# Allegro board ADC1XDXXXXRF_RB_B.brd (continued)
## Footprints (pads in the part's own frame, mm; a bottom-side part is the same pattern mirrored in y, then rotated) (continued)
C6P6MMX6P6MM
  rect 3.81x1.27 smd: 1(-2.625,0) 2(2.625,0)
C10P3MMX10P3MM
  rect 4.15x1.9 smd: 1(-3.875,0) 2(3.875,0)
C0402
  rect 0.889x0.711 smd: 1(-0.648,0) 2(0.648,0)
C0402_NO_SS
  rect 0.406x0.508 smd: 1(-0.508,0) 2(0.508,0)
C0603
  rect 0.813x0.965 smd: 1(-0.711,0) 2(0.711,0)
C0805
  rect 1.27x1.27 smd: 1(-1.067,0) 2(1.067,0)
C1206
  rect 1.524x1.524 smd: 1(-1.651,0) 2(1.651,0)
C1210
  rect 1.626x2.54 smd: 1(-1.714,0) 2(1.714,0)
C3216
  rect 1.6x1.803 smd: 1(-1.6,0) 2(1.6,0)
CAP_C-CASE
  rect 2.692x3.404 smd: 1(-2.743,0) 2(2.743,0)
CHOKE_CM2545-B
  rect 2.032x2.032 hole 1.524: 1(-3.81,1.27)
  round 2.032 hole 1.524: 2(-3.81,-1.27) 3(3.81,-1.27) 4(3.81,1.27)
CONN_SEAM_040
  round 1.27 hole 1.295 unplated: (-27.191,0) (27.191,3.048)
  round 0.635 smd: A1(-24.765,-5.715) A2(-23.495,-5.715) A3(-22.225,-5.715) A4(-20.955,-5.715) A5(-19.685,-5.715) A6(-18.415,-5.715) A7(-17.145,-5.715) A8(-15.875,-5.715) A9(-14.605,-5.715) A10(-13.335,-5.715) A11(-12.065,-5.715) A12(-10.795,-5.715) A13(-9.525,-5.715) A14(-8.255,-5.715) A15(-6.985,-5.715) A16(-5.715,-5.715) A17(-4.445,-5.715) A18(-3.175,-5.715) A19(-1.905,-5.715) A20(-0.635,-5.715) A21(0.635,-5.715) A22(1.905,-5.715) A23(3.175,-5.715) A24(4.445,-5.715) A25(5.715,-5.715) A26(6.985,-5.715) A27(8.255,-5.715) A28(9.525,-5.715) A29(10.795,-5.715) A30(12.065,-5.715) A31(13.335,-5.715) A32(14.605,-5.715) A33(15.875,-5.715) A34(17.145,-5.715) A35(18.415,-5.715) A36(19.685,-5.715) A37(20.955,-5.715) A38(22.225,-5.715) A39(23.495,-5.715) A40(24.765,-5.715) B1(-24.765,-4.445) B2(-23.495,-4.445) B3(-22.225,-4.445) B4(-20.955,-4.445) B5(-19.685,-4.445) B6(-18.415,-4.445) B7(-17.145,-4.445) B8(-15.875,-4.445) B9(-14.605,-4.445) B10(-13.335,-4.445) B11(-12.065,-4.445) B12(-10.795,-4.445) B13(-9.525,-4.445) B14(-8.255,-4.445) B15(-6.985,-4.445) B16(-5.715,-4.445) B17(-4.445,-4.445) B18(-3.175,-4.445) B19(-1.905,-4.445) B20(-0.635,-4.445) B21(0.635,-4.445) B22(1.905,-4.445) B23(3.175,-4.445) B24(4.445,-4.445) B25(5.715,-4.445) B26(6.985,-4.445) B27(8.255,-4.445) B28(9.525,-4.445) B29(10.795,-4.445) B30(12.065,-4.445) B31(13.335,-4.445) B32(14.605,-4.445) B33(15.875,-4.445) B34(17.145,-4.445) B35(18.415,-4.445) B36(19.685,-4.445) B37(20.955,-4.445) B38(22.225,-4.445) B39(23.495,-4.445) B40(24.765,-4.445) C1(-24.765,-3.175) C2(-23.495,-3.175) C3(-22.225,-3.175) C4(-20.955,-3.175) C5(-19.685,-3.175) C6(-18.415,-3.175) C7(-17.145,-3.175) C8(-15.875,-3.175) C9(-14.605,-3.175) C10(-13.335,-3.175) C11(-12.065,-3.175) C12(-10.795,-3.175) C13(-9.525,-3.175) C14(-8.255,-3.175) C15(-6.985,-3.175) C16(-5.715,-3.175) C17(-4.445,-3.175) C18(-3.175,-3.175) C19(-1.905,-3.175) C20(-0.635,-3.175) C21(0.635,-3.175) C22(1.905,-3.175) C23(3.175,-3.175) C24(4.445,-3.175) C25(5.715,-3.175) C26(6.985,-3.175) C27(8.255,-3.175) C28(9.525,-3.175) C29(10.795,-3.175) C30(12.065,-3.175) C31(13.335,-3.175) C32(14.605,-3.175) C33(15.875,-3.175) C34(17.145,-3.175) C35(18.415,-3.175) C36(19.685,-3.175) C37(20.955,-3.175) C38(22.225,-3.175) C39(23.495,-3.175) C40(24.765,-3.175) D1(-24.765,-1.905) D2(-23.495,-1.905) D3(-22.225,-1.905) D4(-20.955,-1.905) D5(-19.685,-1.905) D6(-18.415,-1.905) D7(-17.145,-1.905) D8(-15.875,-1.905) D9(-14.605,-1.905) D10(-13.335,-1.905) D11(-12.065,-1.905) D12(-10.795,-1.905) D13(-9.525,-1.905) D14(-8.255,-1.905) D15(-6.985,-1.905) D16(-5.715,-1.905) D17(-4.445,-1.905) D18(-3.175,-1.905) D19(-1.905,-1.905) D20(-0.635,-1.905) D21(0.635,-1.905) D22(1.905,-1.905) D23(3.175,-1.905) D24(4.445,-1.905) D25(5.715,-1.905) D26(6.985,-1.905) D27(8.255,-1.905) D28(9.525,-1.905) D29(10.795,-1.905) D30(12.065,-1.905) D31(13.335,-1.905) D32(14.605,-1.905) D33(15.875,-1.905) D34(17.145,-1.905) D35(18.415,-1.905) D36(19.685,-1.905) D37(20.955,-1.905) D38(22.225,-1.905) D39(23.495,-1.905) D40(24.765,-1.905) E1(-24.765,-0.635) E2(-23.495,-0.635) E3(-22.225,-0.635) E4(-20.955,-0.635) E5(-19.685,-0.635) E6(-18.415,-0.635) E7(-17.145,-0.635) E8(-15.875,-0.635) E9(-14.605,-0.635) E10(-13.335,-0.635) E11(-12.065,-0.635) E12(-10.795,-0.635) E13(-9.525,-0.635) E14(-8.255,-0.635) E15(-6.985,-0.635) E16(-5.715,-0.635) E17(-4.445,-0.635) E18(-3.175,-0.635) E19(-1.905,-0.635) E20(-0.635,-0.635) E21(0.635,-0.635) E22(1.905,-0.635) E23(3.175,-0.635) E24(4.445,-0.635) E25(5.715,-0.635) E26(6.985,-0.635) E27(8.255,-0.635) E28(9.525,-0.635) E29(10.795,-0.635) E30(12.065,-0.635) E31(13.335,-0.635) E32(14.605,-0.635) E33(15.875,-0.635) E34(17.145,-0.635) E35(18.415,-0.635) E36(19.685,-0.635) E37(20.955,-0.635) E38(22.225,-0.635) E39(23.495,-0.635) E40(24.765,-0.635) F1(-24.765,0.635) F2(-23.495,0.635) F3(-22.225,0.635) F4(-20.955,0.635) F5(-19.685,0.635) F6(-18.415,0.635) F7(-17.145,0.635) F8(-15.875,0.635) F9(-14.605,0.635) F10(-13.335,0.635) F11(-12.065,0.635) F12(-10.795,0.635) F13(-9.525,0.635) F14(-8.255,0.635) F15(-6.985,0.635) F16(-5.715,0.635) F17(-4.445,0.635) F18(-3.175,0.635) F19(-1.905,0.635) F20(-0.635,0.635) F21(0.635,0.635) F22(1.905,0.635) F23(3.175,0.635) F24(4.445,0.635) F25(5.715,0.635) F26(6.985,0.635) F27(8.255,0.635) F28(9.525,0.635) F29(10.795,0.635) F30(12.065,0.635) F31(13.335,0.635) F32(14.605,0.635) F33(15.875,0.635) F34(17.145,0.635) F35(18.415,0.635) F36(19.685,0.635) F37(20.955,0.635) F38(22.225,0.635) F39(23.495,0.635) F40(24.765,0.635) G1(-24.765,1.905) G2(-23.495,1.905) G3(-22.225,1.905) G4(-20.955,1.905) G5(-19.685,1.905) G6(-18.415,1.905) G7(-17.145,1.905) G8(-15.875,1.905) G9(-14.605,1.905) G10(-13.335,1.905) G11(-12.065,1.905) G12(-10.795,1.905) G13(-9.525,1.905) G14(-8.255,1.905) G15(-6.985,1.905) G16(-5.715,1.905) G17(-4.445,1.905) G18(-3.175,1.905) G19(-1.905,1.905) G20(-0.635,1.905) G21(0.635,1.905) G22(1.905,1.905) G23(3.175,1.905) G24(4.445,1.905) G25(5.715,1.905) G26(6.985,1.905) G27(8.255,1.905) G28(9.525,1.905) G29(10.795,1.905) G30(12.065,1.905) G31(13.335,1.905) G32(14.605,1.905) G33(15.875,1.905) G34(17.145,1.905) G35(18.415,1.905) G36(19.685,1.905) G37(20.955,1.905) G38(22.225,1.905) G39(23.495,1.905) G40(24.765,1.905) H1(-24.765,3.175) H2(-23.495,3.175) H3(-22.225,3.175) H4(-20.955,3.175) H5(-19.685,3.175) H6(-18.415,3.175) H7(-17.145,3.175) H8(-15.875,3.175) H9(-14.605,3.175) H10(-13.335,3.175) H11(-12.065,3.175) H12(-10.795,3.175) H13(-9.525,3.175) H14(-8.255,3.175) H15(-6.985,3.175) H16(-5.715,3.175) H17(-4.445,3.175) H18(-3.175,3.175) H19(-1.905,3.175) H20(-0.635,3.175) H21(0.635,3.175) H22(1.905,3.175) H23(3.175,3.175) H24(4.445,3.175) H25(5.715,3.175) H26(6.985,3.175) H27(8.255,3.175) H28(9.525,3.175) H29(10.795,3.175) H30(12.065,3.175) H31(13.335,3.175) H32(14.605,3.175) H33(15.875,3.175) H34(17.145,3.175) H35(18.415,3.175) H36(19.685,3.175) H37(20.955,3.175) H38(22.225,3.175) H39(23.495,3.175) H40(24.765,3.175) J1(-24.765,4.445) J2(-23.495,4.445) J3(-22.225,4.445) J4(-20.955,4.445) J5(-19.685,4.445) J6(-18.415,4.445) J7(-17.145,4.445) J8(-15.875,4.445) J9(-14.605,4.445) J10(-13.335,4.445) J11(-12.065,4.445) J12(-10.795,4.445) J13(-9.525,4.445) J14(-8.255,4.445) J15(-6.985,4.445) J16(-5.715,4.445) J17(-4.445,4.445) J18(-3.175,4.445) J19(-1.905,4.445) J20(-0.635,4.445) J21(0.635,4.445) J22(1.905,4.445) J23(3.175,4.445) J24(4.445,4.445) J25(5.715,4.445) J26(6.985,4.445) J27(8.255,4.445) J28(9.525,4.445) J29(10.795,4.445) J30(12.065,4.445) J31(13.335,4.445) J32(14.605,4.445) J33(15.875,4.445) J34(17.145,4.445) J35(18.415,4.445) J36(19.685,4.445) J37(20.955,4.445) J38(22.225,4.445) J39(23.495,4.445) J40(24.765,4.445) K1(-24.765,5.715) K2(-23.495,5.715) K3(-22.225,5.715) K4(-20.955,5.715) K5(-19.685,5.715) K6(-18.415,5.715) K7(-17.145,5.715) K8(-15.875,5.715) K9(-14.605,5.715) K10(-13.335,5.715) K11(-12.065,5.715) K12(-10.795,5.715) K13(-9.525,5.715) K14(-8.255,5.715) K15(-6.985,5.715) K16(-5.715,5.715) K17(-4.445,5.715) K18(-3.175,5.715) K19(-1.905,5.715) K20(-0.635,5.715) K21(0.635,5.715) K22(1.905,5.715) K23(3.175,5.715) K24(4.445,5.715) K25(5.715,5.715) K26(6.985,5.715) K27(8.255,5.715) K28(9.525,5.715) K29(10.795,5.715) K30(12.065,5.715) K31(13.335,5.715) K32(14.605,5.715) K33(15.875,5.715) K34(17.145,5.715) K35(18.415,5.715) K36(19.685,5.715) K37(20.955,5.715) K38(22.225,5.715) K39(23.495,5.715) K40(24.765,5.715)
DO214_AB
  rect 2.794x3.81 smd: 1(-3.594,0) 2(3.594,0)
EIA_481
  rect 3.988x5.512 smd: 1(-4.242,0) 2(4.242,0)
HC49US
  round 1.524 hole 0.787: 1(2.413,0) 2(-2.413,0)
JACK_POWER
  rect 2.388x1.676 hole 1.626x0.914: 1(0,5.994) 2(0,0)
  rect 1.676x2.388 hole 0.914x1.626: 3(4.699,2.997)
LLP14_P5MM_4X4_EP
  rect 0.61x0.254 smd: 1(-1.9,1.5) 2(-1.9,1) 3(-1.9,0.5) 4(-1.9,0) 5(-1.9,-0.5) 6(-1.9,-1) 7(-1.9,-1.5) 8(1.9,-1.5) 9(1.9,-1) 10(1.9,-0.5) 11(1.9,0) 12(1.9,0.5) 13(1.9,1) 14(1.9,1.5)
  rect 2.591x2.997 smd: 15(0,0)
LLP39_P5MM_6X6
  rect 0.254x0.508 smd: 1(2,2.65) 2(1.5,2.65) 3(1,2.65) 4(0.5,2.65) 5(0,2.65) 6(-0.5,2.65) 7(-1,2.65) 8(-1.5,2.65) 9(-2,2.65) 19(-2,-2.65) 20(-1.5,-2.65) 21(-1,-2.65) 22(-0.5,-2.65) 23(0,-2.65) 24(0.5,-2.65) 25(1,-2.65) 26(1.5,-2.65) 27(2,-2.65)
  rect 0.508x0.254 smd: 10(-2.65,2) 11(-2.65,1.5) 14(-2.65,0) 15(-2.65,-0.5) 16(-2.65,-1) 17(-2.65,-1.5) 18(-2.65,-2) 28(2.65,-2) 29(2.65,-1.5) 30(2.65,-1) 31(2.65,-0.5) 32(2.65,0) 33(2.65,0.5) 34(2.65,1) 35(2.65,1.5) 36(2.65,2)
  rect 1.118x0.254 smd: 12(-2.35,1) 13(-2.35,0.5)
  rect 0.406x4.191 smd: 37(1.9,0)
  rect 2.794x4.191 smd: 38(-0.1,0)
  rect 0.305x0.762 smd: 39(-1.95,-0.25)
OSC_100M_5X7
  rect 1.803x2.007 smd: 1(2.54,2.101) 2(-2.54,2.101) 3(-2.54,-2.101) 4(2.54,-2.101)
R0402_NO_SS
  rect 0.406x0.508 smd: 1(-0.508,0) 2(0.508,0)
R0603
  rect 0.813x0.965 smd: 1(-0.711,0) 2(0.711,0)
R1206
  rect 1.524x1.524 smd: 1(-1.651,0) 2(1.651,0)
RF_SMA_END_LAUNCH
  rect 5.08x2.413 smd: 1(0,-4.318) 2(0,4.318)
  rect 5.08x1.803 smd: 3(0,0)
SC-MKT-MF05A
  rect 0.991x0.686 smd: 1(-1.295,0.953) 2(-1.295,0) 3(-1.295,-0.953) 4(1.295,-0.953) 5(1.295,0.953)
SC-MKT-TJ5A
  rect 1.067x2.413 smd: 1(-3.404,-5.588) 2(-1.702,-5.588) 3(0,-5.588) 4(1.702,-5.588) 5(3.404,-5.588)
  rect 5.588x6.35 smd: 6(0,3.632)
SHDR6X1
  rect 1.524x1.524 hole 1.016: 1(-12.7,0)
  round 1.524 hole 1.016: 2(-12.7,-2.54) 3(-12.7,-5.08) 4(-12.7,-7.62) 5(-12.7,-10.16) 6(-12.7,-12.7)
SM_7PIN_FTR
  rect 3.734x0.762 smd: 1(-1.13,3.81) 2(1.13,2.54) 3(-1.13,1.27) 4(1.13,0) 5(-1.13,-1.27) 6(1.13,-2.54) 7(-1.13,-3.81)
SM_JUMPER
  rect 0.457x0.457 smd: 1(-0.292,0) 2(0.292,0)
SMA_V_CLR
  round 0.81 smd: 1(0,0)
  round 2.032 hole 1.499: 2(2.54,2.54) 3(-2.54,2.54) 4(-2.54,-2.54) 5(2.54,-2.54)
SOCKET_BGA_05_292_B025
  round 5.08 hole 3.048: (-21.209,14.224) (-21.209,-14.224) (21.209,14.224) (21.209,-14.224)
  round 1.981 hole 1.981 unplated: (-5.715,-15.189) (5.08,15.189)
  round 0.635 smd: A1(-12.065,-12.065) A2(-12.065,-10.795) A3(-12.065,-9.525) A4(-12.065,-8.255) A5(-12.065,-6.985) A6(-12.065,-5.715) A7(-12.065,-4.445) A8(-12.065,-3.175) A9(-12.065,-1.905) A10(-12.065,-0.635) A11(-12.065,0.635) A12(-12.065,1.905) A13(-12.065,3.175) A14(-12.065,4.445) A15(-12.065,5.715) A16(-12.065,6.985) A17(-12.065,8.255) A18(-12.065,9.525) A19(-12.065,10.795) A20(-12.065,12.065) B1(-10.795,-12.065) B2(-10.795,-10.795) B3(-10.795,-9.525) B4(-10.795,-8.255) B5(-10.795,-6.985) B6(-10.795,-5.715) B7(-10.795,-4.445) B8(-10.795,-3.175) B9(-10.795,-1.905) B10(-10.795,-0.635) B11(-10.795,0.635) B12(-10.795,1.905) B13(-10.795,3.175) B14(-10.795,4.445) B15(-10.795,5.715) B16(-10.795,6.985) B17(-10.795,8.255) B18(-10.795,9.525) B19(-10.795,10.795) B20(-10.795,12.065) C1(-9.525,-12.065) C2(-9.525,-10.795) C3(-9.525,-9.525) C4(-9.525,-8.255) C5(-9.525,-6.985) C6(-9.525,-5.715) C7(-9.525,-4.445) C8(-9.525,-3.175) C9(-9.525,-1.905) C10(-9.525,-0.635) C11(-9.525,0.635) C12(-9.525,1.905) C13(-9.525,3.175) C14(-9.525,4.445) C15(-9.525,5.715) C16(-9.525,6.985) C17(-9.525,8.255) C18(-9.525,9.525) C19(-9.525,10.795) C20(-9.525,12.065) D1(-8.255,-12.065) D2(-8.255,-10.795) D3(-8.255,-9.525) D4(-8.255,-8.255) D5(-8.255,-6.985) D6(-8.255,-5.715) D7(-8.255,-4.445) D8(-8.255,-3.175) D9(-8.255,-1.905) D10(-8.255,-0.635) D11(-8.255,0.635) D12(-8.255,1.905) D13(-8.255,3.175) D14(-8.255,4.445) D15(-8.255,5.715) D16(-8.255,6.985) D17(-8.255,8.255) D18(-8.255,9.525) D19(-8.255,10.795) D20(-8.255,12.065) E1(-6.985,-12.065) E2(-6.985,-10.795) E3(-6.985,-9.525) E4(-6.985,-8.255) E17(-6.985,8.255) E18(-6.985,9.525) E19(-6.985,10.795) E20(-6.985,12.065) F1(-5.715,-12.065) F2(-5.715,-10.795) F3(-5.715,-9.525) F4(-5.715,-8.255) F17(-5.715,8.255) F18(-5.715,9.525) F19(-5.715,10.795) F20(-5.715,12.065) G1(-4.445,-12.065) G2(-4.445,-10.795) G3(-4.445,-9.525) G4(-4.445,-8.255) G17(-4.445,8.255) G18(-4.445,9.525) G19(-4.445,10.795) G20(-4.445,12.065) H1(-3.175,-12.065) H2(-3.175,-10.795) H3(-3.175,-9.525) H4(-3.175,-8.255) H8(-3.175,-3.175) H9(-3.175,-1.905) H10(-3.175,-0.635) H11(-3.175,0.635) H12(-3.175,1.905) H13(-3.175,3.175) H17(-3.175,8.255) H18(-3.175,9.525) H19(-3.175,10.795) H20(-3.175,12.065) J1(-1.905,-12.065) J2(-1.905,-10.795) J3(-1.905,-9.525) J4(-1.905,-8.255) J8(-1.905,-3.175) J9(-1.905,-1.905) J10(-1.905,-0.635) J11(-1.905,0.635) J12(-1.905,1.905) J13(-1.905,3.175) J17(-1.905,8.255) J18(-1.905,9.525) J19(-1.905,10.795) J20(-1.905,12.065) K1(-0.635,-12.065) K2(-0.635,-10.795) K3(-0.635,-9.525) K4(-0.635,-8.255) K8(-0.635,-3.175) K9(-0.635,-1.905) K10(-0.635,-0.635) K11(-0.635,0.635) K12(-0.635,1.905) K13(-0.635,3.175) K17(-0.635,8.255) K18(-0.635,9.525) K19(-0.635,10.795) K20(-0.635,12.065) L1(0.635,-12.065) L2(0.635,-10.795) L3(0.635,-9.525) L4(0.635,-8.255) L8(0.635,-3.175) L9(0.635,-1.905) L10(0.635,-0.635) L11(0.635,0.635) L12(0.635,1.905) L13(0.635,3.175) L17(0.635,8.255) L18(0.635,9.525) L19(0.635,10.795) L20(0.635,12.065) M1(1.905,-12.065) M2(1.905,-10.795) M3(1.905,-9.525) M4(1.905,-8.255) M8(1.905,-3.175) M9(1.905,-1.905) M10(1.905,-0.635) M11(1.905,0.635) M12(1.905,1.905) M13(1.905,3.175) M17(1.905,8.255) M18(1.905,9.525) M19(1.905,10.795) M20(1.905,12.065) N1(3.175,-12.065) N2(3.175,-10.795) N3(3.175,-9.525) N4(3.175,-8.255) N8(3.175,-3.175) N9(3.175,-1.905) N10(3.175,-0.635) N11(3.175,0.635) N12(3.175,1.905) N13(3.175,3.175) N17(3.175,8.255) N18(3.175,9.525) N19(3.175,10.795) N20(3.175,12.065) P1(4.445,-12.065) P2(4.445,-10.795) P3(4.445,-9.525) P4(4.445,-8.255) P17(4.445,8.255) P18(4.445,9.525) P19(4.445,10.795) P20(4.445,12.065) R1(5.715,-12.065) R2(5.715,-10.795) R3(5.715,-9.525) R4(5.715,-8.255) R17(5.715,8.255) R18(5.715,9.525) R19(5.715,10.795) R20(5.715,12.065) T1(6.985,-12.065) T2(6.985,-10.795) T3(6.985,-9.525) T4(6.985,-8.255) T17(6.985,8.255) T18(6.985,9.525) T19(6.985,10.795) T20(6.985,12.065) U1(8.255,-12.065) U2(8.255,-10.795) U3(8.255,-9.525) U4(8.255,-8.255) U5(8.255,-6.985) U6(8.255,-5.715) U7(8.255,-4.445) U8(8.255,-3.175) U9(8.255,-1.905) U10(8.255,-0.635) U11(8.255,0.635) U12(8.255,1.905) U13(8.255,3.175) U14(8.255,4.445) U15(8.255,5.715) U16(8.255,6.985) U17(8.255,8.255) U18(8.255,9.525) U19(8.255,10.795) U20(8.255,12.065) V1(9.525,-12.065) V2(9.525,-10.795) V3(9.525,-9.525) V4(9.525,-8.255) V5(9.525,-6.985) V6(9.525,-5.715) V7(9.525,-4.445) V8(9.525,-3.175) V9(9.525,-1.905) V10(9.525,-0.635) V11(9.525,0.635) V12(9.525,1.905) V13(9.525,3.175) V14(9.525,4.445) V15(9.525,5.715) V16(9.525,6.985) V17(9.525,8.255) V18(9.525,9.525) V19(9.525,10.795) V20(9.525,12.065) W1(10.795,-12.065) W2(10.795,-10.795) W3(10.795,-9.525) W4(10.795,-8.255) W5(10.795,-6.985) W6(10.795,-5.715) W7(10.795,-4.445) W8(10.795,-3.175) W9(10.795,-1.905) W10(10.795,-0.635) W11(10.795,0.635) W12(10.795,1.905) W13(10.795,3.175) W14(10.795,4.445) W15(10.795,5.715) W16(10.795,6.985) W17(10.795,8.255) W18(10.795,9.525) W19(10.795,10.795) W20(10.795,12.065) Y1(12.065,-12.065) Y2(12.065,-10.795) Y3(12.065,-9.525) Y4(12.065,-8.255) Y5(12.065,-6.985) Y6(12.065,-5.715) Y7(12.065,-4.445) Y8(12.065,-3.175) Y9(12.065,-1.905) Y10(12.065,-0.635) Y11(12.065,0.635) Y12(12.065,1.905) Y13(12.065,3.175) Y14(12.065,4.445) Y15(12.065,5.715) Y16(12.065,6.985) Y17(12.065,8.255) Y18(12.065,9.525) Y19(12.065,10.795) Y20(12.065,12.065)
SOD_123_21
  rect 0.914x1.219 smd: 1(1.638,0) 2(-1.638,0)
SOIC6_026_WG049_L079
  rect 0.33x0.406 smd: 1(-0.495,0.66) 2(-0.495,0) 3(-0.495,-0.66) 4(0.495,-0.66) 5(0.495,0) 6(0.495,0.66)
SOIC8
  rect 1.27x0.635 smd: 1(-2.477,1.905) 2(-2.477,0.635) 3(-2.477,-0.635) 4(-2.477,-1.905) 5(2.477,-1.905) 6(2.477,-0.635) 7(2.477,0.635) 8(2.477,1.905)
SOIC8_050_WG244_L200_EP
  rect 1.905x0.61 smd: 1(-2.781,1.905) 2(-2.781,0.635) 3(-2.781,-0.635) 4(-2.781,-1.905) 5(2.781,-1.905) 6(2.781,-0.635) 7(2.781,0.635) 8(2.781,1.905)
  rect 2.286x2.286 smd: 9(0,0)
SOT23-STX
  rect 0.711x0.991 smd: 1(-0.95,-1.3) 2(0,-1.3) 3(0.95,-1.3) 4(0.95,1.3) 5(-0.95,1.3)
SOT_23_6
  rect 0.991x0.686 smd: 1(-1.295,0.953) 2(-1.295,0) 3(-1.295,-0.953) 4(1.295,-0.953) 5(1.295,0) 6(1.295,0.953)
SW_2P_6X3P5
  round 1.803 hole 1.295: 1(0,0) 2(6.502,0)
SW_TH_RA_7101
  round 2.54 hole 1.778: 1(-4.699,-6.858) 2(0,-6.858) 3(4.699,-6.858)
  round 2.413 hole 1.651: 4(-2.54,5.842) 5(2.54,5.842)
TH_2_HDR1X2_M_STR_100
  rect 1.524x1.524 hole 1.016: 1(0,0)
  round 1.524 hole 1.016: 2(0,-2.54)
TH_10_HDR2X5_M_STR_100
  rect 1.524x1.524 hole 1.016: 1(-1.27,5.08)
  round 1.524 hole 1.016: 2(1.27,5.08) 3(-1.27,2.54) 4(1.27,2.54) 5(-1.27,0) 6(1.27,0) 7(-1.27,-2.54) 8(1.27,-2.54) 9(-1.27,-5.08) 10(1.27,-5.08)
TP40
  round 1.524 hole 1.016: 1(0,0)
TP_SMD_S35X28
  rect 0.889x0.711 smd: 1(0,0)
TSSOP8_65M_WG4P9_L3
  rect 0.991x0.4 smd: 1(-2.45,0.975) 2(-2.45,0.325) 3(-2.45,-0.325) 4(-2.45,-0.975) 5(2.45,-0.975) 6(2.45,-0.325) 7(2.45,0.325) 8(2.45,0.975)
TSSOP16_65M_WG6P4_L5
  rect 1.778x0.432 smd: 1(-2.97,2.275) 2(-2.97,1.625) 3(-2.97,0.975) 4(-2.97,0.325) 5(-2.97,-0.325) 6(-2.97,-0.975) 7(-2.97,-1.625) 8(-2.97,-2.275) 9(2.97,-2.275) 10(2.97,-1.625) 11(2.97,-0.975) 12(2.97,-0.325) 13(2.97,0.325) 14(2.97,0.975) 15(2.97,1.625) 16(2.97,2.275)
  rect 2.997x2.997 smd: 17(0,0)
TSSOP20_65M_WG6P4_L6P5_EP
  rect 1.778x0.432 smd: 1(-2.97,2.925) 2(-2.97,2.275) 3(-2.97,1.625) 4(-2.97,0.975) 5(-2.97,0.325) 6(-2.97,-0.325) 7(-2.97,-0.975) 8(-2.97,-1.625) 9(-2.97,-2.275) 10(-2.97,-2.925) 11(2.97,-2.925) 12(2.97,-2.275) 13(2.97,-1.625) 14(2.97,-0.975) 15(2.97,-0.325) 16(2.97,0.325) 17(2.97,0.975) 18(2.97,1.625) 19(2.97,2.275) 20(2.97,2.925)
  rect 2.997x4.191 smd: 21(0,0)
TSSOP48_50M_WG20_L12
  rect 1.27x0.305 smd: 1(-9.9,5.75) 2(-9.9,5.25) 3(-9.9,4.75) 4(-9.9,4.25) 5(-9.9,3.75) 6(-9.9,3.25) 7(-9.9,2.75) 8(-9.9,2.25) 9(-9.9,1.75) 10(-9.9,1.25) 11(-9.9,0.75) 12(-9.9,0.25) 13(-9.9,-0.25) 14(-9.9,-0.75) 15(-9.9,-1.25) 16(-9.9,-1.75) 17(-9.9,-2.25) 18(-9.9,-2.75) 19(-9.9,-3.25) 20(-9.9,-3.75) 21(-9.9,-4.25) 22(-9.9,-4.75) 23(-9.9,-5.25) 24(-9.9,-5.75) 25(9.9,-5.75) 26(9.9,-5.25) 27(9.9,-4.75) 28(9.9,-4.25) 29(9.9,-3.75) 30(9.9,-3.25) 31(9.9,-2.75) 32(9.9,-2.25) 33(9.9,-1.75) 34(9.9,-1.25) 35(9.9,-0.75) 36(9.9,-0.25) 37(9.9,0.25) 38(9.9,0.75) 39(9.9,1.25) 40(9.9,1.75) 41(9.9,2.25) 42(9.9,2.75) 43(9.9,3.25) 44(9.9,3.75) 45(9.9,4.25) 46(9.9,4.75) 47(9.9,5.25) 48(9.9,5.75)
unnamed#2
  round 1.27 smd: (0,0)
USB-JACK-B
  rect 1.524x1.524 hole 1.016: 1(1.25,1.999)
  round 1.524 hole 1.016: 2(-1.25,1.999) 3(-1.25,0) 4(1.25,0)
  round 3.048 hole 2.337: 5(-6.02,-2.71) 6(6.02,-2.71)
VIA85D55
  round 3.2 hole 2.692: 1(0,0)

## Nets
1V2VCC_INT: C128.1 C129.1 C130.1 C131.1 C132.1 C134.1 C135.1 C184.1 C243.1(POS) C253.2 C299.1 C300.1 C301.1 C302.1 C303.1 C304.1 C305.1 C306.1 C307.1 C308.1 C309.1 C310.1 C311.1 C312.1 C313.1 C314.1 C315.1 C316.1 C317.1 C322.1(POS) L8.2 U5.J10(VCCINT5) U5.J11(VCCINT11) U5.J16(VCCINT19) U5.J17(VCCINT23) U5.K9(VCCINT1) U5.K10(VCCINT6) U5.K17(VCCINT24) U5.K18(VCCINT29) U5.L9(VCCINT2) U5.L10(VCCINT7) U5.L11(VCCINT12) U5.L16(VCCINT20) U5.L17(VCCINT25) U5.L18(VCCINT30) U5.M12(VCCINT15) U5.M15(VCCINT17) U5.R12(VCCINT16) U5.R15(VCCINT18) U5.T9(VCCINT3) U5.T10(VCCINT8) U5.T11(VCCINT13) U5.T16(VCCINT21) U5.T17(VCCINT26) U5.T18(VCCINT31) U5.U9(VCCINT4) U5.U10(VCCINT9) U5.U17(VCCINT27) U5.U18(VCCINT32) U5.V10(VCCINT10) U5.V11(VCCINT14) U5.V16(VCCINT22) U5.V17(VCCINT28)
1V8IO: C102.1 C103.1 C104.1 C105.1 C106.1 C107.1 C162.1 C163.1 C182.1(POS) C183.1 C185.2 C253.1 C254.2 C255.2 C256.2 C275.1 C276.1(POS) C324.1 C362.1 C363.1 J4.1 J4.4 J4.7 J4.10 J4.13 J4.16 J4.19 J4.22 J4.25 J4.28 R98.1 U5.AA22(VCCO_AA22_7) U5.AA25(VCCO_AA25_7) U5.AB19(VCCO_AB19_7) U5.AE19(VCCO_AE19_7) U5.AE22(VCCO_AE22_7) U5.V19(VCCO_V19_7) U5.W17(VCCO_W17_7) U5.W18(VCCO_W18_7) U14.4(VCCINT-1) U14.15(VCCINT-2) U14.34(VCCINT-3) U15.5(OUTPUT)
1V9AC: C52.1 J23.4 J36.2 J37.2 U1.R3(VA-C1) U1.R4(VA-C2)
1V9ANA: C1.1 C2.1 C3.1 C4.1 C5.1 C6.1 C7.1 C323.1 J23.6 J38.2 J39.2 J44.1 U1.A2(VA1) U1.A6(VA2) U1.B6(VA3) U1.D8(VA4) U1.D9(VA5) U1.E1(VA6) U1.F1(VA7) U1.H4(VA8) U1.N4(VA9) U1.R1(VA10) U1.T1(VA11) U1.U8(VA12) U1.U9(VA13) U1.W6(VA14) U1.Y2(VA15) U1.Y6(VA16)
1V9AT: C34.1 C35.1 C36.1 C37.1 C38.1 C39.1 C40.1 C41.1 J23.2 J34.2 J35.2 U1.C6(VA-T13) U1.G1(VA-T1) U1.G3(VA-T2) U1.G4(VA-T3) U1.H2(VA-T4) U1.J3(VA-T5) U1.K3(VA-T6) U1.L3(VA-T7) U1.M3(VA-T8) U1.N2(VA-T9) U1.P1(VA-T10) U1.P3(VA-T11) U1.P4(VA-T12)
1V9DR: C18.1 C19.1 C20.1 C21.1 C22.1 C23.1 C24.1 C25.1 C26.1 C27.1 C28.1 C29.1 C30.1 C254.1 C255.1 C256.1 J23.10 J42.2 J43.2 U1.A11(VDR1) U1.A15(VDR2) U1.C18(VDR3) U1.D11(VDR4) U1.D15(VDR5) U1.D17(VDR6) U1.J17(VDR7) U1.J20(VDR8) U1.R17(VDR9) U1.R20(VDR10) U1.T17(VDR11) U1.U11(VDR12) U1.U15(VDR13) U1.U16(VDR14) U1.Y11(VDR15) U1.Y15(VDR16)
1V9ENC: C46.1 C47.1 C48.1 C49.1 J23.8 J40.2 J41.2 U1.A8(VENC1) U1.B9(VENC2) U1.C8(VENC3) U1.V8(VENC4) U1.W9(VENC5) U1.Y8(VENC6)
2V5IO: C82.1 C83.1 C84.1 C85.1 C86.1 C87.1 C89.1 C90.1 C91.1 C92.1 C93.1 C94.1 C95.1 C96.1 C97.1 C99.1 C100.1 C101.1 C114.1 C115.1 C116.1 C117.1 C118.1 C119.1 C120.1 C121.1 C122.1 C123.1 C124.1 C125.1 C126.1 C169.1(POS) C170.1 C179.2 C180.1 C181.1 C249.2 C250.2 C251.2 C252.2 C257.1 C258.1 C259.1 C260.1 C271.1 C272.1 C273.1 C274.1 C277.1 C278.1 C279.1 C280.1 C281.1 C282.1 C283.1 C284.1 C285.1 C286.1 C287.1 C288.1 C290.1(POS) C295.1 C296.1 C297.1 C325.2 C326.2 C327.2 C364.1 C365.1 J155.2 J156.2 L6.2 R32.1 R33.1 R35.1 R36.1 R37.1 R86.1 R87.1 R91.1 R104.1 U5.AB11(VCCO_AB11_2) U5.AB16(VCCO_AB16_2) U5.AF17(AVDD_SM) U5.B5(VCCO_B5_6) U5.B8(VCCO_B8_6) U5.B11(VCCO_B11_3) U5.B16(VCCO_B16_3) U5.B19(VCCO_B19_5) U5.B22(VCCO_B22_5) U5.E8(VCCO_E8_6) U5.E11(VCCO_E11_1) U5.E16(VCCO_E16_1) U5.E19(VCCO_E19_5) U5.F2(VCCO_F2_6) U5.F5(VCCO_F5_6) U5.F22(VCCO_F22_5) U5.F25(VCCO_F25_5) U5.H9(VCCO_H9_6) U5.H10(VCCO_H10_6) U5.H11(VCCAUX5) U5.H16(VCCAUX9) U5.H17(VCCAUX11) U5.H18(VCCO_H18_5) U5.H19(VCCO_H19_5) U5.J8(VCCO_J8_6) U5.J12(VCCAUX7) U5.J19(VCCO_J19_5) U5.K8(VCCO_K8_10) U5.K19(VCCO_K19_9) U5.L2(VCCO_L2_10) U5.L5(VCCO_L5_10) U5.L22(VCCO_L22_9) U5.L25(VCCO_L25_9) U5.M9(VCCAUX1) U5.M18(VCCO_M18_9) U5.N1(VCCO_N1_10) U5.N9(VCCAUX2) U5.N18(VCCAUX12) U5.P9(VCCAUX3) U5.P18(VCCAUX13) U5.P26(VCCO_P26_9) U5.R9(VCCO_R9_10) U5.R18(VCCAUX14) U5.T2(VCCO_T2_10) U5.T5(VCCO_T5_10) U5.T22(VCCO_T22_9) U5.T25(VCCO_T25_9) U5.U8(VCCO_U8_10) U5.U19(VCCO_U19_9) U5.V15(VCCAUX8) U5.W10(VCCAUX4) U5.W11(VCCAUX6) U5.W16(VCCAUX10) U15.4(INPUT) U15.8(NS/D)
3V0PLL: C144.1 C145.2 C153.1 C156.2 C231.1 C232.1(POS) L13.2 R65.1 TP15.1 U12.1(VCCDIG) U12.16(VCCVCO) U12.22(VCCBUF) U12.27(VCCPLL)
3V3IO: C74.1 C78.1 C80.1 C81.1 C88.1 C98.1 C108.1 C109.1 C110.1 C111.1 C166.1 C167.1 C168.1(POS) C171.1 C172.1 C173.1 C174.1 C178.2 C249.1 C250.1 C251.1 C252.1 C261.1 C262.1 C263.1 C264.1 C265.1 C291.1 C292.1 C293.1 C294.1(POS) C325.1 C326.1 C327.1 J6.1 L5.1 R29.1 R34.1 R38.1 R40.1 R47.2 R48.2 R49.2 R50.2 R51.2 R52.2 R54.2 R55.2 R81.1 R85.1 R88.1 R115.2 U5.AA2(VCCO_AA2_8) U5.AA5(VCCO_AA5_8) U5.AB8(VCCO_AB8_8) U5.AD15(VCCOAD15_4) U5.AE5(VCCO_AE5_8) U5.AE8(VCCO_AE8_8) U5.AE11(VCCOAE11_4) U5.J15(VCCO_J15_0) U5.V8(VCCO_V8_8) U5.V12(VCCO_V12_0) U5.W8(VCCO_W8_8) U5.W9(VCCO_W9_8) U14.8(VCCO-1) U14.24(VCCJ) U14.30(VCCO-2) U14.38(VCCO-3) U14.45(VCCO-4) Y2.4(VDD)
3V3USB: C54.1 C55.1 C56.1 C57.1 C58.1 C59.1 C60.1 C61.1 C62.1 C63.1 C67.1 C68.1 C216.1 C217.1(POS) L1.2 L11.2 R15.2 R18.1 R19.2 R20.1 R21.2 R142.2 U2.2(VCC1) U2.26(VCC2) U2.43(VCC3) U2.48(VCC4) U2.64(VCC5) U2.68(VCC6) U2.81(VCC7) U2.100(VCC8) U2.101(WAKEUP) U2.107(VCC9) U3.5(VCC) U4.8(VCC)
3V3USI1: C77.1 C136.1 C224.1 C225.1(POS) C241.1(POS) C245.1 C246.1 J13.3 L12.2 U8.2(VDD) U24.8(VCC) U25.8(VCC)
5V0USI1: C210.1 C211.1(POS) C221.1 C222.1 J13.1 L3.2 U17.1(EN) U20.4(INPUT)
GND: C1.2 C1_LF.2 C2.2 C3.2 C4.2 C5.2 C6.2 C7.2 C18.2 C19.2 C20.2 C21.2 C22.2 C23.2 C24.2 C25.2 C26.2 C27.2 C28.2 C29.2 C30.2 C34.2 C35.2 C36.2 C37.2 C38.2 C39.2 C40.2 C41.2 C46.2 C47.2 C48.2 C49.2 C52.2 C54.2 C55.2 C56.2 C57.2 C58.2 C59.2 C60.2 C61.2 C62.2 C63.2 C64.2(NEG) C65.2 C66.2 C67.2 C68.2 C69.1 C70.2 C71.2 C72.2 C73.2 C74.2 C77.2 C78.2 C79.2 C80.2 C81.2 C82.2 C83.2 C84.2 C85.2 C86.2 C87.2 C88.2 C89.2 C90.2 C91.2 C92.2 C93.2 C94.2 C95.2 C96.2 C97.2 C98.2 C99.2 C100.2 C101.2 C102.2 C103.2 C104.2 C105.2 C106.2 C107.2 C108.2 C109.2 C110.2 C111.2 C114.2 C115.2 C116.2 C117.2 C118.2 C119.2 C120.2 C121.2 C122.2 C123.2 C124.2 C125.2 C126.2 C128.2 C129.2 C130.2 C131.2 C132.2 C134.2 C135.2 C136.2 C137.1 C138.1 C140.1 C143.2 C144.2 C145.1 C149.1 C153.2 C155.1 C156.1 C157.2(NEG) C158.2 C159.2 C160.2 C161.2 C162.2 C163.2 C166.2 C167.2 C168.2(NEG) C169.2(NEG) C170.2 C171.2 C172.2 C173.2 C174.2 C175.2 C176.2 C177.2 C180.2 C181.2 C182.2(NEG) C183.2 C184.2 C186.2 C187.2 C188.1 C190.2 C192.2 C193.2 C194.2(NEG) C195.2 C196.2 C197.2 C198.2 C201.2 C205.2 C206.2 C207.2 C208.2 C209.2(NEG) C210.2 C211.2(NEG) C213.2 C214.2 C215.2(NEG) C216.2 C217.2(NEG) C218.2 C220.2 C221.2 C222.2 C223.2(NEG) C224.2 C225.2(NEG) C227.2 C228.2 C229.2 C230.2(NEG) C231.2 C232.2(NEG) C234.2 C235.2 C236.2 C237.2 C239.2(NEG) C240.2 C241.2(NEG) C242.2(NEG) C243.2(NEG) C244.2 C245.2 C246.2 C248.2 C257.2 C258.2 C259.2 C260.2 C261.2 C262.2 C263.2 C264.2 C265.2 C266.2 C267.2 C268.2 C269.2 C270.2 C271.2 C272.2 C273.2 C274.2 C275.2 C276.2(NEG) C277.2 C278.2 C279.2 C280.2 C281.2 C282.2 C283.2 C284.2 C285.2 C286.2 C287.2 C288.2 C290.2(NEG) C291.2 C292.2 C293.2 C294.2(NEG) C295.2 C296.2 C297.2 C299.2 C300.2 C301.2 C302.2 C303.2 C304.2 C305.2 C306.2 C307.2 C308.2 C309.2 C310.2 C311.2 C312.2 C313.2 C314.2 C315.2 C316.2 C317.2 C322.2(NEG) C323.2 C324.2 C362.2 C363.2 C364.2 D1.1(ANODE) D2.1(ANODE) D3.1(ANODE) D5.1(ANODE) DCLKQ+.2(SHIELD2) DCLKQ+.3(SHIELD3) DCLKQ+.4(SHIELD4) DCLKQ+.5(SHIELD5) DCLKQ-.2(SHIELD2) DCLKQ-.3(SHIELD3) DCLKQ-.4(SHIELD4) DCLKQ-.5(SHIELD5) FMC.A1 FMC.A4 FMC.A5 FMC.A8 FMC.A9 FMC.A12 FMC.A13 FMC.A16 FMC.A17 FMC.A20 FMC.A21 FMC.A24 FMC.A25 FMC.A28 FMC.A29 FMC.A32 FMC.A33 FMC.A36 FMC.A37 FMC.A40 FMC.B2 FMC.B3 FMC.B6 FMC.B7 FMC.B10 FMC.B11 FMC.B14 FMC.B15 FMC.B18 FMC.B19 FMC.B22 FMC.B23 FMC.B26 FMC.B27 FMC.B30 FMC.B31 FMC.B34 FMC.B35 FMC.B38 FMC.B39 FMC.C1 FMC.C4 FMC.C5 FMC.C8 FMC.C9 FMC.C12 FMC.C13 FMC.C16 FMC.C17 FMC.C20 FMC.C21 FMC.C24 FMC.C25 FMC.C28 FMC.C29 FMC.C32 FMC.C33 FMC.C36 FMC.C38 FMC.C40 FMC.D2 FMC.D3 FMC.D6 FMC.D7 FMC.D10 FMC.D13 FMC.D16 FMC.D19 FMC.D22 FMC.D25 FMC.D28 FMC.D37 FMC.D39 FMC.E1 FMC.E4 FMC.E5 FMC.E8 FMC.E11 FMC.E14 FMC.E17 FMC.E20 FMC.E23 FMC.E26 FMC.E29 FMC.E32 FMC.E35 FMC.E38 FMC.E40 FMC.F2 FMC.F3 FMC.F6 FMC.F9 FMC.F12 FMC.F15 FMC.F18 FMC.F21 FMC.F24 FMC.F27 FMC.F30 FMC.F33 FMC.F36 FMC.F39 FMC.G1 FMC.G4 FMC.G5 FMC.G8 FMC.G11 FMC.G14 FMC.G17 FMC.G20 FMC.G23 FMC.G26 FMC.G29 FMC.G32 FMC.G35 FMC.G38 FMC.G40 FMC.H2 FMC.H3 FMC.H6 FMC.H9 FMC.H12 FMC.H15 FMC.H18 FMC.H21 FMC.H24 FMC.H27 FMC.H30 FMC.H33 FMC.H36 FMC.H39 FMC.J1 FMC.J4 FMC.J5 FMC.J8 FMC.J11 FMC.J14 FMC.J17 FMC.J20 FMC.J23 FMC.J26 FMC.J29 FMC.J32 FMC.J35 FMC.J38 FMC.J40 FMC.K2 FMC.K3 FMC.K6 FMC.K9 FMC.K12 FMC.K15 FMC.K18 FMC.K21 FMC.K24 FMC.K27 FMC.K30 FMC.K33 FMC.K36 FMC.K39 J2.4(GND) J4.3(1) J4.6(4) J4.9(7) J4.12(10) J4.15(13) J4.18(16) J4.21(19) J4.24(22) J4.27(25) J4.30(28) J6.6 J7.1 J7.2 J8.1 J8.2 J9.1 J9.2 J10.1 J10.2 J15.1 J17.1 J18.2 J18.4 J18.6 J18.8 J18.10 J19.1 J19.2 J25.5 J25.6 J26.1 J26.2 J27.1 J27.2 J28.1 J28.2 J29.1 J29.2 J30.1 J30.2 J31.1 J31.2 J32.1 J32.2 J44.2 J44.4 J44.6 J44.8 J44.10 J163.1 J163.2 L9.3 LD10.2(CATHODE) MT1.1 MT2.1 MT3.1 MT4.1 MT5.1 R2_LF.1 R20.3 R23.2 R24.1 R38.3 R40.3 R59.2 R67.2 R68.2 R69.2 R70.2 R71.2 R78.1 R84.2 R89.1 R90.1 R92.1 R95.1 R97.1 R107.1 R108.1 R109.1 R111.1 R117.1 R124.1 R126.2 R130.2 R132.2 R135.2 R137.2 R150.2 R155.1 R156.2 R196.2 R197.2 R205.1 R208.1 R211.1 R214.1 R217.1 R220.1 R223.1 R226.1 RCLK+.2(SHIELD2) RCLK+.3(SHIELD3) RCLK+.4(SHIELD4) RCLK+.5(SHIELD5) RCLK-.2(SHIELD2) RCLK-.3(SHIELD3) RCLK-.4(SHIELD4) RCLK-.5(SHIELD5) RCOUT1+.2(SHIELD2) RCOUT1+.3(SHIELD3) RCOUT1+.4(SHIELD4) RCOUT1+.5(SHIELD5) RCOUT1-.2(SHIELD2) RCOUT1-.3(SHIELD3) RCOUT1-.4(SHIELD4) RCOUT1-.5(SHIELD5) SW1.2 T2.1 T2.3 T2.5 TP5.1 TP6.1 TP7.1 TP8.1 TP9.1 TP10.1 TP11.1 U1.A1(GND1) U1.A7(GND2) U1.A9(GND-E1) U1.A13(DRGND1) U1.A17(DRGND2) U1.A20(DRGND3) U1.B2(GND3) U1.B7(GND4) U1.B8(GND-E2) U1.C9(GND-E3) U1.D4(GND5) U1.D5(GND6) U1.D13(DRGND4) U1.D16(DRGND5) U1.E4(GND7) U1.E17(DRGND6) U1.F2(GND-T1) U1.F17(DRGND7) U1.F20(DRGND8) U1.G2(GND-T2) U1.H3(GND-T3) U1.H8(GND8) U1.H9(GND9) U1.H10(GND10) U1.H11(GND11) U1.H12(GND12) U1.H13(GND13) U1.J2(GND-T4) U1.J8(GND14) U1.J9(GND15) U1.J10(GND16) U1.J11(GND17) U1.J12(GND18) U1.J13(GND19) U1.K1(GND20) U1.K4(GND-T5) U1.K8(GND21) U1.K9(GND22) U1.K10(GND23) U1.K11(GND24) U1.K12(GND25) U1.K13(GND26) U1.L1(GND27) U1.L4(GND-T6) U1.L8(GND28) U1.L9(GND29) U1.L10(GND30) U1.L11(GND31) U1.L12(GND32) U1.L13(GND33) U1.M2(GND-T7) U1.M8(GND34) U1.M9(GND35) U1.M10(GND36) U1.M11(GND37) U1.M12(GND38) U1.M13(GND39) U1.M17(DRGND9) U1.M20(DRGND10) U1.N3(GND-T8) U1.N8(GND40) U1.N9(GND41) U1.N10(GND42) U1.N11(GND43) U1.N12(GND44) U1.N13(GND45) U1.P2(GND-T9) U1.R2(GND-T10) U1.T2(GND-C1) U1.T3(GND-C2) U1.T4(GND46) U1.U1(GND-C3) U1.U4(GND47) U1.U5(GND48) U1.U13(DRGND11) U1.U17(DRGND12) U1.V9(GND-E4) U1.V18(DRGND13) U1.W2(GND49) U1.W7(GND50) U1.W8(GND-E5) U1.Y1(GND51) U1.Y7(GND52) U1.Y9(GND-E6) U1.Y13(DRGND14) U1.Y17(DRGND15) U1.Y20(DRGND16) U2.3(GND1) U2.13(AGND1) U2.20(AGND2) U2.27(GND2) U2.33(RSVD_GND) U2.49(GND3) U2.58(GND4) U2.65(GND5) U2.80(GND6) U2.93(GND7) U2.116(GND8) U2.125(GND9) U3.1(GND1) U3.2(GND2) U4.2(A1) U4.3(A2) U4.4(GND) U4.7(WP) U5.A2(GND4) U5.A13(GND34) U5.A14(GND46) U5.A25(GND84) U5.AA6(GND13) U5.AA21(GND80) U5.AB12(GND33) U5.AB15(GND65) U5.AD9(GND15) U5.AD18(GND77) U5.AD24(GND83) U5.AE1(GND3) U5.AE2(GND6) U5.AE15(VREFN_SM) U5.AE16(VREFP_SM) U5.AE17(AVSS_SM) U5.AE25(GND86) U5.AE26(GND90) U5.AF2(GND7) U5.AF13(GND45) U5.AF14(GND57) U5.AF15(VN_SM) U5.AF16(VP_SM) U5.AF25(GND87) U5.B1(GND1) U5.B2(GND5) U5.B25(GND85) U5.B26(GND88) U5.C3(GND8) U5.C9(GND14) U5.C18(GND76) U5.E12(GND26) U5.E15(GND58) U5.F6(GND11) U5.F21(GND78) U5.J3(GND9) U5.J13(GND35) U5.J14(GND47) U5.J24(GND81) U5.K11(GND20) U5.K12(GND27) U5.K13(GND36) U5.K14(GND48) U5.K15(GND59) U5.K16(GND66) U5.L12(GND28) U5.L13(GND37) U5.L14(GND49) U5.L15(GND60) U5.M10(GND16) U5.M11(GND21) U5.M13(GND38) U5.M14(GND50) U5.M16(GND67) U5.M17(GND72) U5.N6(GND12) U5.N10(GND17) U5.N11(GND22) U5.N12(GND29) U5.N13(GND39) U5.N14(GND51) U5.N15(GND61) U5.N16(GND68) U5.N17(GND73) U5.N26(GND89) U5.P1(GND2) U5.P10(GND18) U5.P11(GND23) U5.P12(GND30) U5.P13(GND40) U5.P14(GND52) U5.P15(GND62) U5.P16(GND69) U5.P17(GND74) U5.P21(GND79) U5.R10(GND19) U5.R11(GND24) U5.R13(GND41) U5.R14(GND53) U5.R16(GND70) U5.R17(GND75) U5.T12(GND31) U5.T13(GND42) U5.T14(GND54) U5.T15(GND63) U5.U11(GND25) U5.U12(GND32) U5.U13(GND43) U5.U14(GND55) U5.U15(GND64) U5.U16(GND71) U5.V3(GND10) U5.V13(GND44) U5.V14(GND56) U5.V24(GND82) U5.Y16(VBATT_0) U8.8(GND) U8.15(PAD) U12.3(GND#3) U12.19(GND#19) U12.20(GND#20) U12.33(TEST) U12.34(GND#34) U12.37(GND#37) U12.38(GND#38) U13.5(GND) U13.17(PAD) U14.2(GND-1) U14.7(GND-2) U14.17(GND-4) U14.23(GND-5) U14.31(GND-6) U14.36(GND-7) U14.46(GND-8) U15.3(GND) U15.9(PAD) U16.10(AGND) U16.13(PGND1) U16.14(PGND2) U16.21(PAD) U17.3(GND) U17.6(DAP) U18.3(GND) U18.9(PAD) U19.3(GND) U19.9(PAD) U20.3(GND) U20.9(PAD) U21.2(GND) U22.3(GND) U22.9(PAD) U23.9(GND1) U23.10(GND2) U23.11(GND3) U23.12(AGND) U23.21(PAD) U24.5(VEE) U25.5(VEE) U29.2(GND) Y2.2(GND) Y3.2(GND)
V4_TCK: J6.4 U5.W12(TCK_0) U14.20(TCK)
V4_TDI: J6.5 R43.1 U14.19(TDI)
V4_TDO: J6.3 U5.Y13(TDO_0)
V4_TMS: J6.2 U5.Y11(TMS_0) U14.21(TMS)
VIN: C158.1 C159.1 C160.1 C187.1 C192.1 C193.1 C207.1 C208.1 C228.1 C229.1 C269.1 C270.1 L4.2 R82.2 U13.11(PVIN1) U13.12(PVIN2) U13.13(PVIN3) U13.14(PVIN4) U16.3(VIN1) U16.4(VIN2) U18.4(INPUT) U22.4(INPUT) U23.5(VIN1) U23.6(VIN2) U23.15(VIN3) U23.16(VIN4) U29.1(VIN) U29.3(ON/O\F\F\)
VINI+: J7.3 U1.H1(VINI+)
VINI-: J8.3 U1.J1(VINI-)
VINQ+: J9.3 U1.N1(VINQ+)
VINQ-: J10.3 U1.M1(VINQ-)
ADC_PWR: R58.2 R59.1 U5.AC24(IO_L16N_7)
ADC_TDIODE+: C76.2 U1.E2(TDIODE+) U8.7(D1+)
ADC_TDIODE-: C75.1 C76.1 U1.F3(TDIODE-) U5.G13(TDN_0) U8.5(D-)
CAL: J4.29(28) R128.1 U5.AD25(IO_L11P_7)
CALDLY: J4.20(19) R5.1 R113.2
CALRUN: U1.B5(CALRUN) U5.AF23(IO_L19P_7)
CLK+: C341.2 U1.U2(CLK+)
CLK-: C342.2 U1.V1(CLK-)
CONF_CCLK: R17.2 R31.1 R81.2 R83.2 R84.1
CONF_DIN: U2.78(PC6/GPIFADR6) U5.G12(D_IN_0) U14.28(D0)
CONF_DONE: R29.2 U2.115(PE7/GPIFADR8) U5.H14(DONE_0) U14.13(C\E\)
CONF_INITB: R34.2 U2.79(PC7/GPIFADR7) U5.G15(INIT_B_0) U14.11(OE/R\S\T\)
CS_N: U2.42(CS_N) U5.AF7(IO_L25N_CC_LC_8)
CY_ADDR0: U2.94(A0) U5.W2(IO_L1P_8)
CY_ADDR1: U2.95(A1) U5.W1(IO_L1N_8)
CY_ADDR2: U2.96(A2) U5.V6(IO_L2P_8)
CY_ADDR3: U2.97(A3) U5.V5(IO_L2N_8)
CY_ADDR4: U2.117(A4) U5.W7(IO_L3P_8)
CY_ADDR5: U2.118(A5) U5.V7(IO_L3N_8)
CY_ADDR6: U2.119(A6) U5.W4(IO_L4P_8)
CY_ADDR7: U2.120(A7) U5.W3(IO_L4N_VREF_8)
CY_ADDR8: U2.126(A8) U5.W6(IO_L5P_8)
CY_ADDR9: U2.127(A9) U5.W5(IO_L5N_8)
CY_ADDR10: U2.128(A10) U5.Y2(IO_L6P_8)
CY_ADDR11: U2.21(A11) U5.Y1(IO_L6N_8)
CY_ADDR12: U2.22(A12) U5.AA4(IO_L7P_8)
CY_ADDR13: U2.23(A13) U5.AA3(IO_L7N_8)
CY_ADDR14: U2.24(A14) U5.Y4(IO_L8P_CC_LC_8)
CY_ADDR15: U2.25(A15) U5.Y3(IO_L8N_CC_LC_8)
CY_CTL3: U2.66(CTL3) U5.AE14(IO_L5P_GC_LC_4)
CY_CTL4: U2.67(CTL4) U5.AE13(IO_L5N_GC_LC_4)
CY_CTL5: U2.98(CTL5) U5.AE10(IO_L6P_GC_LC_4)
CY_DATA0: U2.59(D0) U5.AF4(IO_L17P_8)
CY_DATA1: U2.60(D1) U5.AE4(IO_L17N_8)
CY_DATA2: U2.61(D2) U5.AD3(IO_L18P_8)
CY_DATA3: U2.62(D3) U5.AC3(IO_L18N_8)
CY_DATA4: U2.63(D4) U5.AF6(IO_L19P_8)
CY_DATA5: U2.86(D5) U5.AF5(IO_L19N_8)
CY_DATA6: U2.87(D6) U5.AA7(IO_L20P_8)
CY_DATA7: U2.88(D7) U5.Y7(IO_L20N_VREF_8)
CY_FD0: U2.44(PB0/FD0) U5.Y6(IO_L9P_CC_LC_8)
CY_FD1: U2.45(PB1/FD1) U5.Y5(IO_L9N_CC_LC_8)
CY_FD2: U2.46(PB2/FD2) U5.AB1(IO_L10P_8)
CY_FD3: U2.47(PB3/FD3) U5.AA1(IO_L10N_8)
CY_FD4: U2.54(PB4/FD4) U5.AC4(IO_L11P_8)
CY_FD5: U2.55(PB5/FD5) U5.AB4(IO_L11N_8)
CY_FD6: U2.56(PB6/FD6) U5.AB3(IO_L12P_8)
CY_FD7: U2.57(PB7/FD7) U5.AB2(IO_L12N_VREF_8)
CY_FD8: U2.102(PD0/FD8) U5.AC5(IO_L13P_8)
CY_FD9: U2.103(PD1/FD9) U5.AB5(IO_L13N_8)
CY_FD10: U2.104(PD2/FD10) U5.AC2(IO_L14P_8)
CY_FD11: U2.105(PD3/FD11) U5.AC1(IO_L14N_8)
CY_FD12: U2.121(PD4/FD12) U5.AF3(IO_L15P_8)
CY_FD13: U2.122(PD5/FD13) U5.AE3(IO_L15N_8)
CY_FD14: U2.123(PD6/FD14) U5.AD2(IO_L16P_8)
CY_FD15: U2.124(PD7/FD15) U5.AD1(IO_L16N_8)
CY_ID0: U2.72(PC0/GPIFADR0) U5.AA9(IO_L21P_8)
CY_ID1: U2.73(PC1/GPIFADR1) U5.Y9(IO_L21N_8)
CY_ID2: U2.74(PC2/GPIFADR2) U5.AD5(IO_L22P_8)
CY_ID3: U2.75(PC3/GPIFADR3) U5.AD4(IO_L22N_8)
CY_REQ: R13.2 U5.AB7(IO_L28N_VREF_8)
CY_VALID: U2.114(PE6/T2EX) U5.AC9(IO_L29P_8)
DCLK_RST+: R131.2 R132.1 R133.2 TP4.1 U1.V2(DCLK_RST+)
DCLK_RST-: R129.2 R130.1 R133.1 TP3.1 U1.W1(DCLK_RST-)
DCLKI+: U1.K19(DCLKI+) U5.A16(IO_L5P_GC_LC_3)
DCLKI-: U1.K20(DCLKI-) U5.A15(IO_L5N_GC_LC_3)
DCLKQ+: R162.1 U5.A10(IO_L6P_GC_LC_3)
DCLKQ+_OUT: DCLKQ+.1(CENTER) R162.3
DCLKQ-: R161.1 U5.B10(IO_L6N_GC_LC_3)
DCLKQ-_OUT: DCLKQ-.1(CENTER) R161.3
DCLKQ_N: R161.2 U1.L20(DCLKQ-)
DCLKQ_P: R162.2 U1.L19(DCLKQ+)
DDRPHASE: J4.17(16) R3.1 R28.2
DES: J4.11(10) R6.1 R26.2
DI+0: R209.2 R210.1 U1.B18(DI0+) U5.N23(IO_L16P_9)
DI+1: R212.2 R213.1 U1.B19(DI1+) U5.M21(IO_L13P_9)
DI+2: U1.C19(DI2+) U5.M23(IO_L14P_9)
DI+3: U1.D18(DI3+) U5.M25(IO_L11P_9)
DI+4: U1.D19(DI4+) U5.L21(IO_L6P_9)
DI+5: U1.E19(DI5+) U5.L24(IO_L10P_9)
DI+6: U1.F18(DI6+) U5.L26(IO_L12P_9)
DI+7: U1.G17(DI7+) U5.K22(IO_L3P_9)
DI+8: U1.G19(DI8+) U5.K24(IO_L7P_9)
DI+9: U1.H17(DI9+) U5.K26(IO_L8P_CC_LC_9)
DI+10: U1.H19(DI10+) U5.J21(IO_L1P_9)
DI+11: U1.J18(DI11+) U5.J23(IO_L2P_9)
DI-0: R209.1 R211.2 U1.C17(DI0-) U5.N22(IO_L16N_9)
DI-1: R212.1 R214.2 U1.B20(DI1-) U5.M20(IO_L13N_9)
DI-2: U1.C20(DI2-) U5.M22(IO_L14N_9)
DI-3: U1.E18(DI3-) U5.M24(IO_L11N_9)
DI-4: U1.D20(DI4-) U5.L20(IO_L6N_9)
DI-5: U1.E20(DI5-) U5.L23(IO_L10N_9)
DI-6: U1.F19(DI6-) U5.M26(IO_L12N_VREF_9)
DI-7: U1.G18(DI7-) U5.K21(IO_L3N_9)
DI-8: U1.G20(DI8-) U5.K23(IO_L7N_9)
DI-9: U1.H18(DI9-) U5.K25(IO_L8N_CC_LC_9)
DI-10: U1.H20(DI10-) U5.J20(IO_L1N_9)
DI-11: U1.J19(DI11-) U5.J22(IO_L2N_9)
DID+0: R203.2 R204.1 U1.A10(DID0+) U5.V26(IO_L32P_9)
DID+1: R206.2 R207.1 U1.C10(DID1+) U5.U25(IO_L28P_9)
DID+2: U1.B11(DID2+) U5.T21(IO_L30P_9)
DID+3: U1.A12(DID3+) U5.T24(IO_L24P_CC_LC_9)
DID+4: U1.C12(DID4+) U5.T26(IO_L26P_9)
DID+5: U1.B13(DID5+) U5.R22(IO_L23P_VRN_9)
DID+6: U1.A14(DID6+) U5.R24(IO_L22P_9)
DID+7: U1.C14(DID7+) U5.R26(IO_L20P_9)
DID+8: U1.B15(DID8+) U5.P23(IO_L19P_9)
DID+9: U1.A16(DID9+) U5.P25(IO_L18P_9)
DID+10: U1.B17(DID10+) U5.N21(IO_L17P_9)
DID+11: U1.A18(DID11+) U5.N25(IO_L15P_9)
DID-0: R203.1 R205.2 U1.B10(DID0-) U5.V25(IO_L32N_9)
DID-1: R206.1 R208.2 U1.D10(DID1-) U5.U24(IO_L28N_VREF_9)
DID-2: U1.C11(DID2-) U5.T20(IO_L30N_9)
DID-3: U1.B12(DID3-) U5.T23(IO_L24N_CC_LC_9)
DID-4: U1.D12(DID4-) U5.U26(IO_L26N_9)
DID-5: U1.C13(DID5-) U5.R21(IO_L23N_VRP_9)
DID-6: U1.B14(DID6-) U5.R23(IO_L22N_9)
DID-7: U1.D14(DID7-) U5.R25(IO_L20N_VREF_9)
DID-8: U1.C15(DID8-) U5.P22(IO_L19N_9)
DID-9: U1.B16(DID9-) U5.P24(IO_L18N_9)
DID-10: U1.C16(DID10-) U5.N20(IO_L17N_9)
DID-11: U1.A19(DID11-) U5.N24(IO_L15N_9)
DQ+0: R215.2 R216.1 U1.W18(DQ0+) U5.D26(IO_L25P_CC_LC_5)
DQ+1: R218.2 R219.1 U1.W19(DQ1+) U5.F20(IO_L19P_5)
DQ+2: U1.V19(DQ2+) U5.E23(IO_L18P_5)
DQ+3: U1.U18(DQ3+) U5.E25(IO_L27P_5)
DQ+4: U1.U19(DQ4+) U5.G19(IO_L17P_5)
DQ+5: U1.T19(DQ5+) U5.F24(IO_L24P_CC_LC_5)
DQ+6: U1.R18(DQ6+) U5.F26(IO_L29P_5)
DQ+7: U1.P17(DQ7+) U5.G22(IO_L23P_VRN_5)
DQ+8: U1.P19(DQ8+) U5.G24(IO_L28P_5)
DQ+9: U1.N17(DQ9+) U5.G26(IO_L31P_5)
DQ+10: U1.N19(DQ10+) U5.H22(IO_L26P_5)
DQ+11: U1.M18(DQ11+) U5.H24(IO_L30P_5)
DQ-0: R215.1 R217.2 U1.V17(DQ0-) U5.D25(IO_L25N_CC_LC_5)
DQ-1: R218.1 R220.2 U1.W20(DQ1-) U5.E20(IO_L19N_5)
DQ-2: U1.V20(DQ2-) U5.E22(IO_L18N_5)
DQ-3: U1.T18(DQ3-) U5.E24(IO_L27N_5)
DQ-4: U1.U20(DQ4-) U5.F19(IO_L17N_5)
DQ-5: U1.T20(DQ5-) U5.F23(IO_L24N_CC_LC_5)
DQ-6: U1.R19(DQ6-) U5.E26(IO_L29N_5)
DQ-7: U1.P18(DQ7-) U5.G21(IO_L23N_VRP_5)
DQ-8: U1.P20(DQ8-) U5.G23(IO_L28N_VREF_5)
DQ-9: U1.N18(DQ9-) U5.G25(IO_L31N_5)
DQ-10: U1.N20(DQ10-) U5.H21(IO_L26N_5)
DQ-11: U1.M19(DQ11-) U5.H23(IO_L30N_5)
DQD+0: R221.2 R222.1 U1.Y10(DQD0+) U5.A20(IO_L13P_5)
DQD+1: R224.2 R225.1 U1.V10(DQD1+) U5.A22(IO_L15P_5)
DQD+2: U1.W11(DQD2+) U5.A24(IO_L8P_CC_LC_5)
DQD+3: U1.Y12(DQD3+) U5.B24(IO_L10P_5)
DQD+4: U1.V12(DQD4+) U5.C20(IO_L2P_5)
DQD+5: U1.W13(DQD5+) U5.C21(IO_L6P_5)
DQD+6: U1.Y14(DQD6+) U5.C26(IO_L20P_5)
DQD+7: U1.V14(DQD7+) U5.D20(IO_L4P_5)
DQD+8: U1.W15(DQD8+) U5.D22(IO_L14P_5)
DQD+9: U1.Y16(DQD9+) U5.D23(IO_L21P_5)
DQD+10: U1.W17(DQD10+) U5.D24(IO_L16P_5)
DQD+11: U1.Y18(DQD11+) U5.E21(IO_L12P_5)
DQD-0: R221.1 R223.2 U1.W10(DQD0-) U5.A19(IO_L13N_5)
DQD-1: R224.1 R226.2 U1.U10(DQD1-) U5.A21(IO_L15N_5)
DQD-2: U1.V11(DQD2-) U5.A23(IO_L8N_CC_LC_5)
DQD-3: U1.W12(DQD3-) U5.B23(IO_L10N_5)
DQD-4: U1.U12(DQD4-) U5.B20(IO_L2N_5)
DQD-5: U1.V13(DQD5-) U5.B21(IO_L6N_5)
DQD-6: U1.W14(DQD6-) U5.C25(IO_L20N_VREF_5)
DQD-7: U1.U14(DQD7-) U5.D19(IO_L4N_VREF_5)
DQD-8: U1.V15(DQD8-) U5.C22(IO_L14N_5)
DQD-9: U1.W16(DQD9-) U5.C23(IO_L21N_5)
DQD-10: U1.V16(DQD10-) U5.C24(IO_L16N_5)
DQD-11: U1.Y19(DQD11-) U5.D21(IO_L12N_VREF_5)
ECE: J4.8(7) R4.1 R46.2
ENABLE1: J14.2 R96.2 R120.1 U23.19(EN)
ENABLE2: J14.4 R121.1 U16.2(SD)
ENABLE3: J14.6 R122.1 U18.8(NS/D) U20.8(NS/D) U22.8(NS/D)
ENABLE26400: C177.1 R96.1 U13.3(EN1) U13.6(EN2)
EXT_TRIG+: R136.2 R137.1 U5.G18(IO_L9P_CC_LC_5)
EXT_TRIG-: R134.2 R135.1 U5.G17(IO_L9N_CC_LC_5)
FIFOADR0: U2.89(PA4/FIFOADR0) U5.AC6(IO_L24P_CC_LC_8)
FIFOADR1: U2.90(PA5/FIFOADR1) U5.AB6(IO_L24N_CC_LC_8)
FLAGA: U2.69(CTL0/FLAGA) U5.Y10(IO_L27P_8)
FLAGB: U2.70(CTL1/FLAGB) U5.AA10(IO_L27N_8)
FLAGC: U2.71(CTL2/FLAGC) U5.AC7(IO_L28P_8)
FLASH_TDO: R43.2 U5.Y12(TDI_0) U14.22(TDO)
FMC_CALRUN: FMC.G18 U5.H6(IO_L29P_6)
FMC_DCLK_DI+: FMC.D20 U5.J2(IO_L4P_10)
FMC_DCLK_DI-: FMC.D21 U5.J1(IO_L4N_VREF_10)
FMC_DCLK_DID+: FMC.G6 U5.P8(IO_L19P_10)
FMC_DCLK_DID-: FMC.G7 U5.N8(IO_L19N_10)
FMC_DCLK_DQ+: FMC.K25 U5.H2(IO_L32P_6)
FMC_DCLK_DQ-: FMC.K26 U5.H1(IO_L32N_6)
FMC_DCLK_DQD+: FMC.F4 U5.A9(IO_L13P_6)
FMC_DCLK_DQD-: FMC.F5 U5.B9(IO_L13N_6)
FMC_DI+0: FMC.C22 U5.N7(IO_L17P_10)
FMC_DI+1: FMC.H22 U5.M6(IO_L13P_10)
FMC_DI+2: FMC.G21 U5.N5(IO_L15P_10)
FMC_DI+3: FMC.H25 U5.M4(IO_L12P_10)
FMC_DI+4: FMC.G24 U5.N3(IO_L14P_10)
FMC_DI+5: FMC.D23 U5.M2(IO_L11P_10)
FMC_DI+6: FMC.H28 U5.L7(IO_L5P_10)
FMC_DI+7: FMC.G27 U5.K7(IO_L3P_10)
FMC_DI+8: FMC.D26 U5.K5(IO_L6P_10)
FMC_DI+9: FMC.C26 U5.J5(IO_L2P_10)
FMC_DI+10: FMC.H31 U5.L1(IO_L10P_10)
FMC_DI+11: FMC.G30 U5.K3(IO_L7P_10)
FMC_DI-0: FMC.C23 U5.M7(IO_L17N_10)
FMC_DI-1: FMC.H23 U5.M5(IO_L13N_10)
FMC_DI-2: FMC.G22 U5.N4(IO_L15N_10)
FMC_DI-3: FMC.H26 U5.M3(IO_L12N_VREF_10)
FMC_DI-4: FMC.G25 U5.N2(IO_L14N_10)
FMC_DI-5: FMC.D24 U5.M1(IO_L11N_10)
FMC_DI-6: FMC.H29 U5.L6(IO_L5N_10)
FMC_DI-7: FMC.G28 U5.K6(IO_L3N_10)
FMC_DI-8: FMC.D27 U5.K4(IO_L6N_10)
FMC_DI-9: FMC.C27 U5.J4(IO_L2N_10)
FMC_DI-10: FMC.H32 U5.K1(IO_L10N_10)
FMC_DI-11: FMC.G31 U5.K2(IO_L7N_10)
FMC_DID+0: FMC.D8 U5.T8(IO_L31P_10)
FMC_DID+1: FMC.H7 U5.T7(IO_L27P_10)
FMC_DID+2: FMC.G9 U5.U6(IO_L32P_10)
FMC_DID+3: FMC.H10 U5.V4(IO_L29P_10)
FMC_DID+4: FMC.D11 U5.T4(IO_L26P_10)
FMC_DID+5: FMC.C10 U5.U3(IO_L28P_10)
FMC_DID+6: FMC.H13 U5.V2(IO_L30P_10)
FMC_DID+7: FMC.G12 U5.P7(IO_L21P_10)
FMC_DID+8: FMC.D14 U5.R4(IO_L20P_10)
FMC_DID+9: FMC.C14 U5.R2(IO_L22P_10)
FMC_DID+10: FMC.H16 U5.P5(IO_L18P_10)
FMC_DID+11: FMC.G15 U5.P3(IO_L16P_10)
FMC_DID-0: FMC.D9 U5.U7(IO_L31N_10)
FMC_DID-1: FMC.H8 U5.T6(IO_L27N_10)
FMC_DID-2: FMC.G10 U5.U5(IO_L32N_10)
FMC_DID-3: FMC.H11 U5.U4(IO_L29N_10)
FMC_DID-4: FMC.D12 U5.T3(IO_L26N_10)
FMC_DID-5: FMC.C11 U5.U2(IO_L28N_VREF_10)
FMC_DID-6: FMC.H14 U5.V1(IO_L30N_10)
FMC_DID-7: FMC.G13 U5.P6(IO_L21N_10)
FMC_DID-8: FMC.D15 U5.R3(IO_L20N_VREF_10)
FMC_DID-9: FMC.C15 U5.R1(IO_L22N_10)
FMC_DID-10: FMC.H17 U5.P4(IO_L18N_10)
FMC_DID-11: FMC.G16 U5.P2(IO_L16N_10)
FMC_DQ+0: FMC.J24 U5.C4(IO_L16P_6)
FMC_DQ+1: FMC.F22 U5.C5(IO_L12P_6)
FMC_DQ+2: FMC.E21 U5.E6(IO_L18P_6)
FMC_DQ+3: FMC.F25 U5.G6(IO_L23P_VRN_6)
FMC_DQ+4: FMC.E24 U5.D3(IO_L22P_6)
FMC_DQ+5: FMC.K28 U5.C2(IO_L20P_6)
FMC_DQ+6: FMC.J27 U5.F4(IO_L27P_6)
FMC_DQ+7: FMC.F28 U5.G4(IO_L28P_6)
FMC_DQ+8: FMC.E27 U5.E1(IO_L26P_6)
FMC_DQ+9: FMC.K31 U5.D10(IO_L1P_6)
FMC_DQ+10: FMC.J30 U5.G2(IO_L30P_6)
FMC_DQ+11: FMC.F31 U5.H4(IO_L31P_6)
FMC_DQ-0: FMC.J25 U5.D4(IO_L16N_6)
FMC_DQ-1: FMC.F23 U5.D5(IO_L12N_VREF_6)
FMC_DQ-2: FMC.E22 U5.E5(IO_L18N_6)
FMC_DQ-3: FMC.F26 U5.G5(IO_L23N_VRP_6)
FMC_DQ-4: FMC.E25 U5.E4(IO_L22N_6)
FMC_DQ-5: FMC.K29 U5.C1(IO_L20N_VREF_6)
FMC_DQ-6: FMC.J28 U5.F3(IO_L27N_6)
FMC_DQ-7: FMC.F29 U5.G3(IO_L28N_VREF_6)
FMC_DQ-8: FMC.E28 U5.F1(IO_L26N_6)
FMC_DQ-9: FMC.K32 U5.C10(IO_L1N_6)
FMC_DQ-10: FMC.J31 U5.G1(IO_L30N_6)
FMC_DQ-11: FMC.F32 U5.H3(IO_L31N_6)
FMC_DQD+0: FMC.E2 U5.F10(IO_L5P_6)
FMC_DQD+1: FMC.K7 U5.E9(IO_L7P_6)
FMC_DQD+2: FMC.J6 U5.F8(IO_L10P_6)
FMC_DQD+3: FMC.F7 U5.D9(IO_L2P_6)
FMC_DQD+4: FMC.E6 U5.D8(IO_L4P_6)
FMC_DQD+5: FMC.K10 U5.B7(IO_L11P_6)
FMC_DQD+6: FMC.J9 U5.A8(IO_L3P_6)
FMC_DQD+7: FMC.F10 U5.F7(IO_L19P_6)
FMC_DQD+8: FMC.E9 U5.E7(IO_L17P_6)
FMC_DQD+9: FMC.K13 U5.A6(IO_L6P_6)
FMC_DQD+10: FMC.J12 U5.A4(IO_L15P_6)
FMC_DQD+11: FMC.F13 U5.A3(IO_L14P_6)
FMC_DQD-0: FMC.E3 U5.E10(IO_L5N_6)
FMC_DQD-1: FMC.K8 U5.F9(IO_L7N_6)
FMC_DQD-2: FMC.J7 U5.G8(IO_L10N_6)
FMC_DQD-3: FMC.F8 U5.C8(IO_L2N_6)
FMC_DQD-4: FMC.E7 U5.D7(IO_L4N_VREF_6)
FMC_DQD-5: FMC.K11 U5.C7(IO_L11N_6)
FMC_DQD-6: FMC.J10 U5.A7(IO_L3N_6)
FMC_DQD-7: FMC.F11 U5.G7(IO_L19N_6)
FMC_DQD-8: FMC.E10 U5.D6(IO_L17N_6)
FMC_DQD-9: FMC.K14 U5.A5(IO_L6N_6)
FMC_DQD-10: FMC.J13 U5.B4(IO_L15N_6)
FMC_DQD-11: FMC.F14 U5.B3(IO_L14N_6)
FMC_ORI+: FMC.H34 U5.J7(IO_L1P_10)
FMC_ORI-: FMC.H35 U5.J6(IO_L1N_10)
FMC_ORQ+: FMC.E30 U5.H8(IO_L21P_6)
FMC_ORQ-: FMC.E31 U5.H7(IO_L21N_6)
FMC_PG_C2M: FMC.D1 J155.1 R155.2 U5.R5(IO_L23N_VRP_10)
FMC_PG_M2C: FMC.F1 J156.1 R156.1 U5.R6(IO_L23P_VRN_10)
FMC_RCOUT1+: FMC.C18 U5.U23(IO_L27P_9)
FMC_RCOUT1-: FMC.C19 U5.V23(IO_L27N_9)
FMC_RCOUT2+: FMC.H19 U5.U22(IO_L29P_9)
FMC_RCOUT2-: FMC.H20 U5.U21(IO_L29N_9)
FPGA_RESET: R15.1 R16.2 U5.AF8(IO_L25P_CC_LC_8)
FSR: J4.14(13) R2.1 R27.2
IFCLK: U2.32(IFCLK) U5.AC10(IO_L2P_GC_LC_4)
JP_1: J18.1 R33.2 U5.AC14(IO_L5P_D7_LC_2)
JP_2: J18.3 R37.2 U5.AD14(IO_L5N_D6_LC_2)
JP_3: J18.5 R36.2 U5.AA12(IO_L6P_D5_LC_2)
JP_4: J18.7 R35.2 U5.AA11(IO_L6N_D4_LC_2)
JP_5: J18.9 R32.2 U5.AC16(IO_L7P_D3_LC_2)
LED_ADC_CAL: ADC_CALIBRATION.2(CATHODE) U5.AE12(IO_L1N_GC_LC_4)
LED_ADC_PWR: ADC_POWER.2(CATHODE) U5.AF12(IO_L1P_GC_LC_4)
LED_DCLK_LOCKED: DCLK_LOCKED.2(CATHODE) U5.AF10(IO_L4N_GC_VREF_LC_4)
LED_ECM_ENA: ECM_ENABLED.2(CATHODE) U5.AD8(IO_L32P_8)
LED_FPGA_OPER: FPGA_OPERATIONAL.2(CATHODE) U5.AF11(IO_L4P_GC_LC_4)
LED_OVERRANGE_I: OVER-RANGE_I-CH.2(CATHODE) U5.AB17(IO_L3P_GC_LC_4)
LED_OVERRANGE_Q: OVER-RANGE_Q-CH.2(CATHODE) U5.AC17(IO_L3N_GC_LC_4)
LED_RCOUT_ENA: RCOUT1/2_ENABLED.2(CATHODE) U5.AC8(IO_L32N_8)
LED_TRIGGER: TRIGGER_ARMED.2(CATHODE) U5.AB10(IO_L2N_GC_LC_4)
LOAD_STATE: R14.2 U5.AE7(IO_L23P_VRN_8)
NDM: J4.26(25) R127.1 U5.AF21(IO_L30P_SM3_7)
ORI+: U1.K17(ORI+) U5.J26(IO_L4P_9)
ORI-: U1.K18(ORI-) U5.J25(IO_L4N_VREF_9)
ORQ+: U1.L17(ORQ+) U5.H26(IO_L32P_5)
ORQ-: U1.L18(ORQ-) U5.H25(IO_L32N_5)
PDI: J4.2(1) R9.1 R44.2
PDQ: J4.5(4) R25.1 R45.2
PKTEND: U2.91(PA6/PKTEND) U5.AE9(IO_L31N_8)
PLL_CE: J162.1 TP20.1 U5.C17(IO_L1P_5)
PLL_LD: J158.1 TP16.1 U5.H5(IO_L29N_6)
PLL_LE: J161.1 TP19.1 U5.D17(IO_L1N_5)
PLL_SCLK: J160.1 TP18.1 U5.G9(IO_L9N_CC_LC_6)
PLL_SDATA: J159.1 TP17.1 U5.G10(IO_L9P_CC_LC_6)
PROGRAMB: R85.2 U2.76(PC4/GPIFADR4) U5.H15(PROG_B_0) U14.6(C\F\)
RCLK+: R145.1 U1.Y4(RCLK+)
RCLK+_IN: R145.2 RCLK+.1(CENTER)
RCLK-: R147.1 U1.W5(RCLK-)
RCLK-_IN: R147.2 RCLK-.1(CENTER)
RCOUT1+: R160.1 U5.B17(IO_L7P_GC_LC_3)
RCOUT1+_OUT: R160.3 RCOUT1+.1(CENTER)
RCOUT1-: R159.1 U5.A17(IO_L7N_GC_LC_3)
RCOUT1-_OUT: R159.3 RCOUT1-.1(CENTER)
RCOUT1N: R159.2 U1.U6(RCOUT1-)
RCOUT1P: R160.2 U1.Y5(RCOUT1+)
RCOUT2+: J5.1 U1.V6(RCOUT2+) U5.C13(IO_L8P_GC_LC_3)
RCOUT2-: J5.2 U1.V7(RCOUT2-) U5.C12(IO_L8N_GC_LC_3)
RD_N: U2.40(RD_N) U5.Y8(IO_L26N_8)
RXD0: J25.4 U2.51(RXD0)
RXD1: J25.3 U2.53(RXD1)
SCL_FROM_CY: J15.8 J17.8 R19.1 U2.36(SCL) U4.6(SCL) U8.13(SMBCLK)
SCLK: J44.5 U1.C5(SCLK) U5.AE24(IO_L22N_7)
SCLK_USI: J15.5 J17.5 U5.F13(IO_L1N_D30_LC_1)
SCS: J44.7 U1.C4(SCS) U5.AF24(IO_L22P_7)
SCS1_USI: J17.3 U5.F14(IO_L1P_D31_LC_1)
SCS2_USI: J15.3 U5.F16(IO_L3P_D27_LC_1)
SDA: J20.1 R22.1 U2.37(SDA) U4.5(SDA)
SDA_FROM_CY: J15.6 J17.6 J20.2 R21.1 R22.2 U8.12(SMBDAT)
SDI: J44.9 U1.B4(SDI) U5.AF22(IO_L30N_SM3_7)
SDI_USI: J15.7 J17.7 U5.F11(IO_L2N_D28_LC_1)
SDO: J44.3 U1.A3(SDO) U5.AF18(IO_L31P_SM2_7)
SDO_USI: J15.4 J17.4 U5.F12(IO_L2P_D29_LC_1)
SLCS_N: U2.92(PA7/FLGD/SLCS_N) U5.AB9(IO_L29N_8)
SLOE: U2.84(PA2/SLOE) U5.AF9(IO_L31P_8)
SLRD: U2.4(RDY0/SLRD) U5.AE6(IO_L30P_8)
SLWR: U2.5(RDY1/SLWR) U5.AD6(IO_L30N_8)
STATE0: U2.108(PE0/T0OUT) U5.AD10(IO_L6N_GC_LC_4)
STATE1: U2.109(PE1/T1OUT) U5.AD17(IO_L7P_GC_VRN_LC_4)
STATE2: U2.110(PE2/T2OUT) U5.AD16(IO_L7N_GC_VRP_LC_4)
STATE3: U2.111(PE3/RXD0OUT) U5.AD11(IO_L8N_GC_CC_LC_4)
TCRIT1: R104.2 U5.AC15(IO_L7N_D2_LC_2) U8.10(TCRIT1)
TCRIT2: R87.2 U5.AC13(IO_L8P_D1_LC_2) U8.11(TCRIT2)
TCRIT3: R86.2 U5.AD13(IO_L8N_D0_LC_2) U8.14(TCRIT3)
TEST1N: R30.1 U5.AA13(IO_L4N_D8_VREF_LC_2) U6.3
TEST1P: R30.2 U5.AB13(IO_L4P_D9_LC_2) U6.1
TEST2N: R39.1 U5.AA15(IO_L3N_D10_LC_2) U6.7
TEST2P: R39.2 U5.AA16(IO_L3P_D11_LC_2) U6.5
TEST3N: R41.1 U5.AC11(IO_L2N_D12_LC_2) U7.3
TEST3P: R41.2 U5.AC12(IO_L2P_D13_LC_2) U7.1
TEST4N: R42.1 U5.AB14(IO_L1N_D14_CC_LC_2) U7.7
TEST4P: R42.2 U5.AA14(IO_L1P_D15_CC_LC_2) U7.5
TPM: J4.23(22) R8.1 R114.2
TXD0: J25.2 U2.50(TXD0)
TXD1: J25.1 U2.52(TXD1)
USB_PWR: C213.1 C214.1 J2.1(VBUS) U19.4(INPUT) U19.8(NS/D)
V_ADC: C242.1(POS) C244.1 C365.2 J23.1 J23.3 J23.5 J23.7 J23.9 J34.1 J35.1 J36.1 J37.1 J38.1 J39.1 J40.1 J41.1 J42.1 J43.1 L14.2 R58.1 R204.2 R207.2 R210.2 R213.2 R216.2 R219.2 R222.2 R225.2
V_USI1: J13.2 J15.2 J17.2
VCMO: J15.9 J17.9 U1.C2(VCMO)
VIO_PRE: C194.1(POS) C195.1 L2.1 L10.2 R105.1 R106.1 U16.12(OUT)
WE_N: U2.41(WR_N) U5.AA8(IO_L26P_8)
N16663533: J27.3 J28.3
N16663537: J29.3 J30.3
N16663541: J31.3 J32.3
N16721567: J2.3(D+) U2.18(DPLUS)
N16721659: J2.2(D-) U2.19(DMINUS)
N16722721: C69.2 J2.5(SHELL_1) J2.6(SHELL_2) R24.2
N16727306: R23.1 U2.35(EA)
N16769321: C164.1 D2.2(CATHODE) L5.2 U13.15(SW1)
N16769692: C175.1 U13.2(SS1)
N16769839: C178.1 R88.2 R89.2 U13.1(FB1)
N16770680: C164.2 U13.16(BST1)
N16772680: C161.1 R82.1 U13.4(AVIN)
N16798185: C188.2 C190.1 U16.1(VCC)
N16802160: R40.2 U5.G16(HSWAPEN_0)
N16802193: C75.2 U5.H13(TDP_0) U8.6(D2+)
N16802234: R31.2 U5.G14(CCLK_0)
N16802239: R38.2 U5.W14(M2_0) U5.W15(M0_0) U5.Y15(M1_0)
N16803121: C191.2 R103.1 U16.6(COMP)
N16805297: C191.1 C202.1 R105.2 R106.2 R107.2 U16.7(FB)
N16805320: R53.1 Y2.3(OUT)
N16807514: C202.2 R103.2
N16809137: R108.2 U16.8(RT)
N16815468: C206.1 U16.9(RAMP)
N16819191: C189.1 U16.20(BST)
N16819385: C189.2 D4.2(CATHODE) L10.1 U16.17(SW1) U16.18(SW2)
N16821177: D4.1(ANODE) U16.15(IS1) U16.16(IS2)
N16824930: C205.1 U16.11(SS)
N16831687: C196.1 C198.1 L2.2 U17.2(IN)
N16860475: C218.1 U18.1(BYPASS)
N16862731: C212.1 R109.2 R110.2 U18.6(ADJ)
N16862763: C209.1(POS) C212.2 L3.1 R110.1 U18.5(OUTPUT)
N16864683: J163.3 R180.1
N16864708: C342.1 T2.4
N16864710: C341.1 T2.6
N16864734: C343.1 R180.2
N16865152: J158.2 U12.30(FTEST/LD)
N16865229: J161.2 U12.10(LE)
N16865231: J160.2 U12.9(CLK)
N16865233: J159.2 U12.8(DATA)
N16865299: J162.2 U12.11(CE)
N16865342: C1_LF.1 C2_LF.1 U12.23(VTUNE) U12.24(CPOUT)
N16865346: C2_LF.2 R2_LF.2 R73.2
N16865743: C137.2 C138.2 C240.1 R65.2 Y3.4(VDD)
N16865780: C321.2 R195.2 R196.1
N16865782: R180.3 R195.1 R197.1
N16906306: C139.1 R66.1 R68.1 R69.1
N16906312: C139.2 U12.31(OSCIN)
N16907733: C165.1 D3.2(CATHODE) L6.1 U13.10(SW2)
N16907748: C176.1 U13.7(SS2)
